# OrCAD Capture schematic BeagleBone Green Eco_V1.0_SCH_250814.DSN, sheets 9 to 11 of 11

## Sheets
9 P04_AM335x 1/3, JTAG: size A2
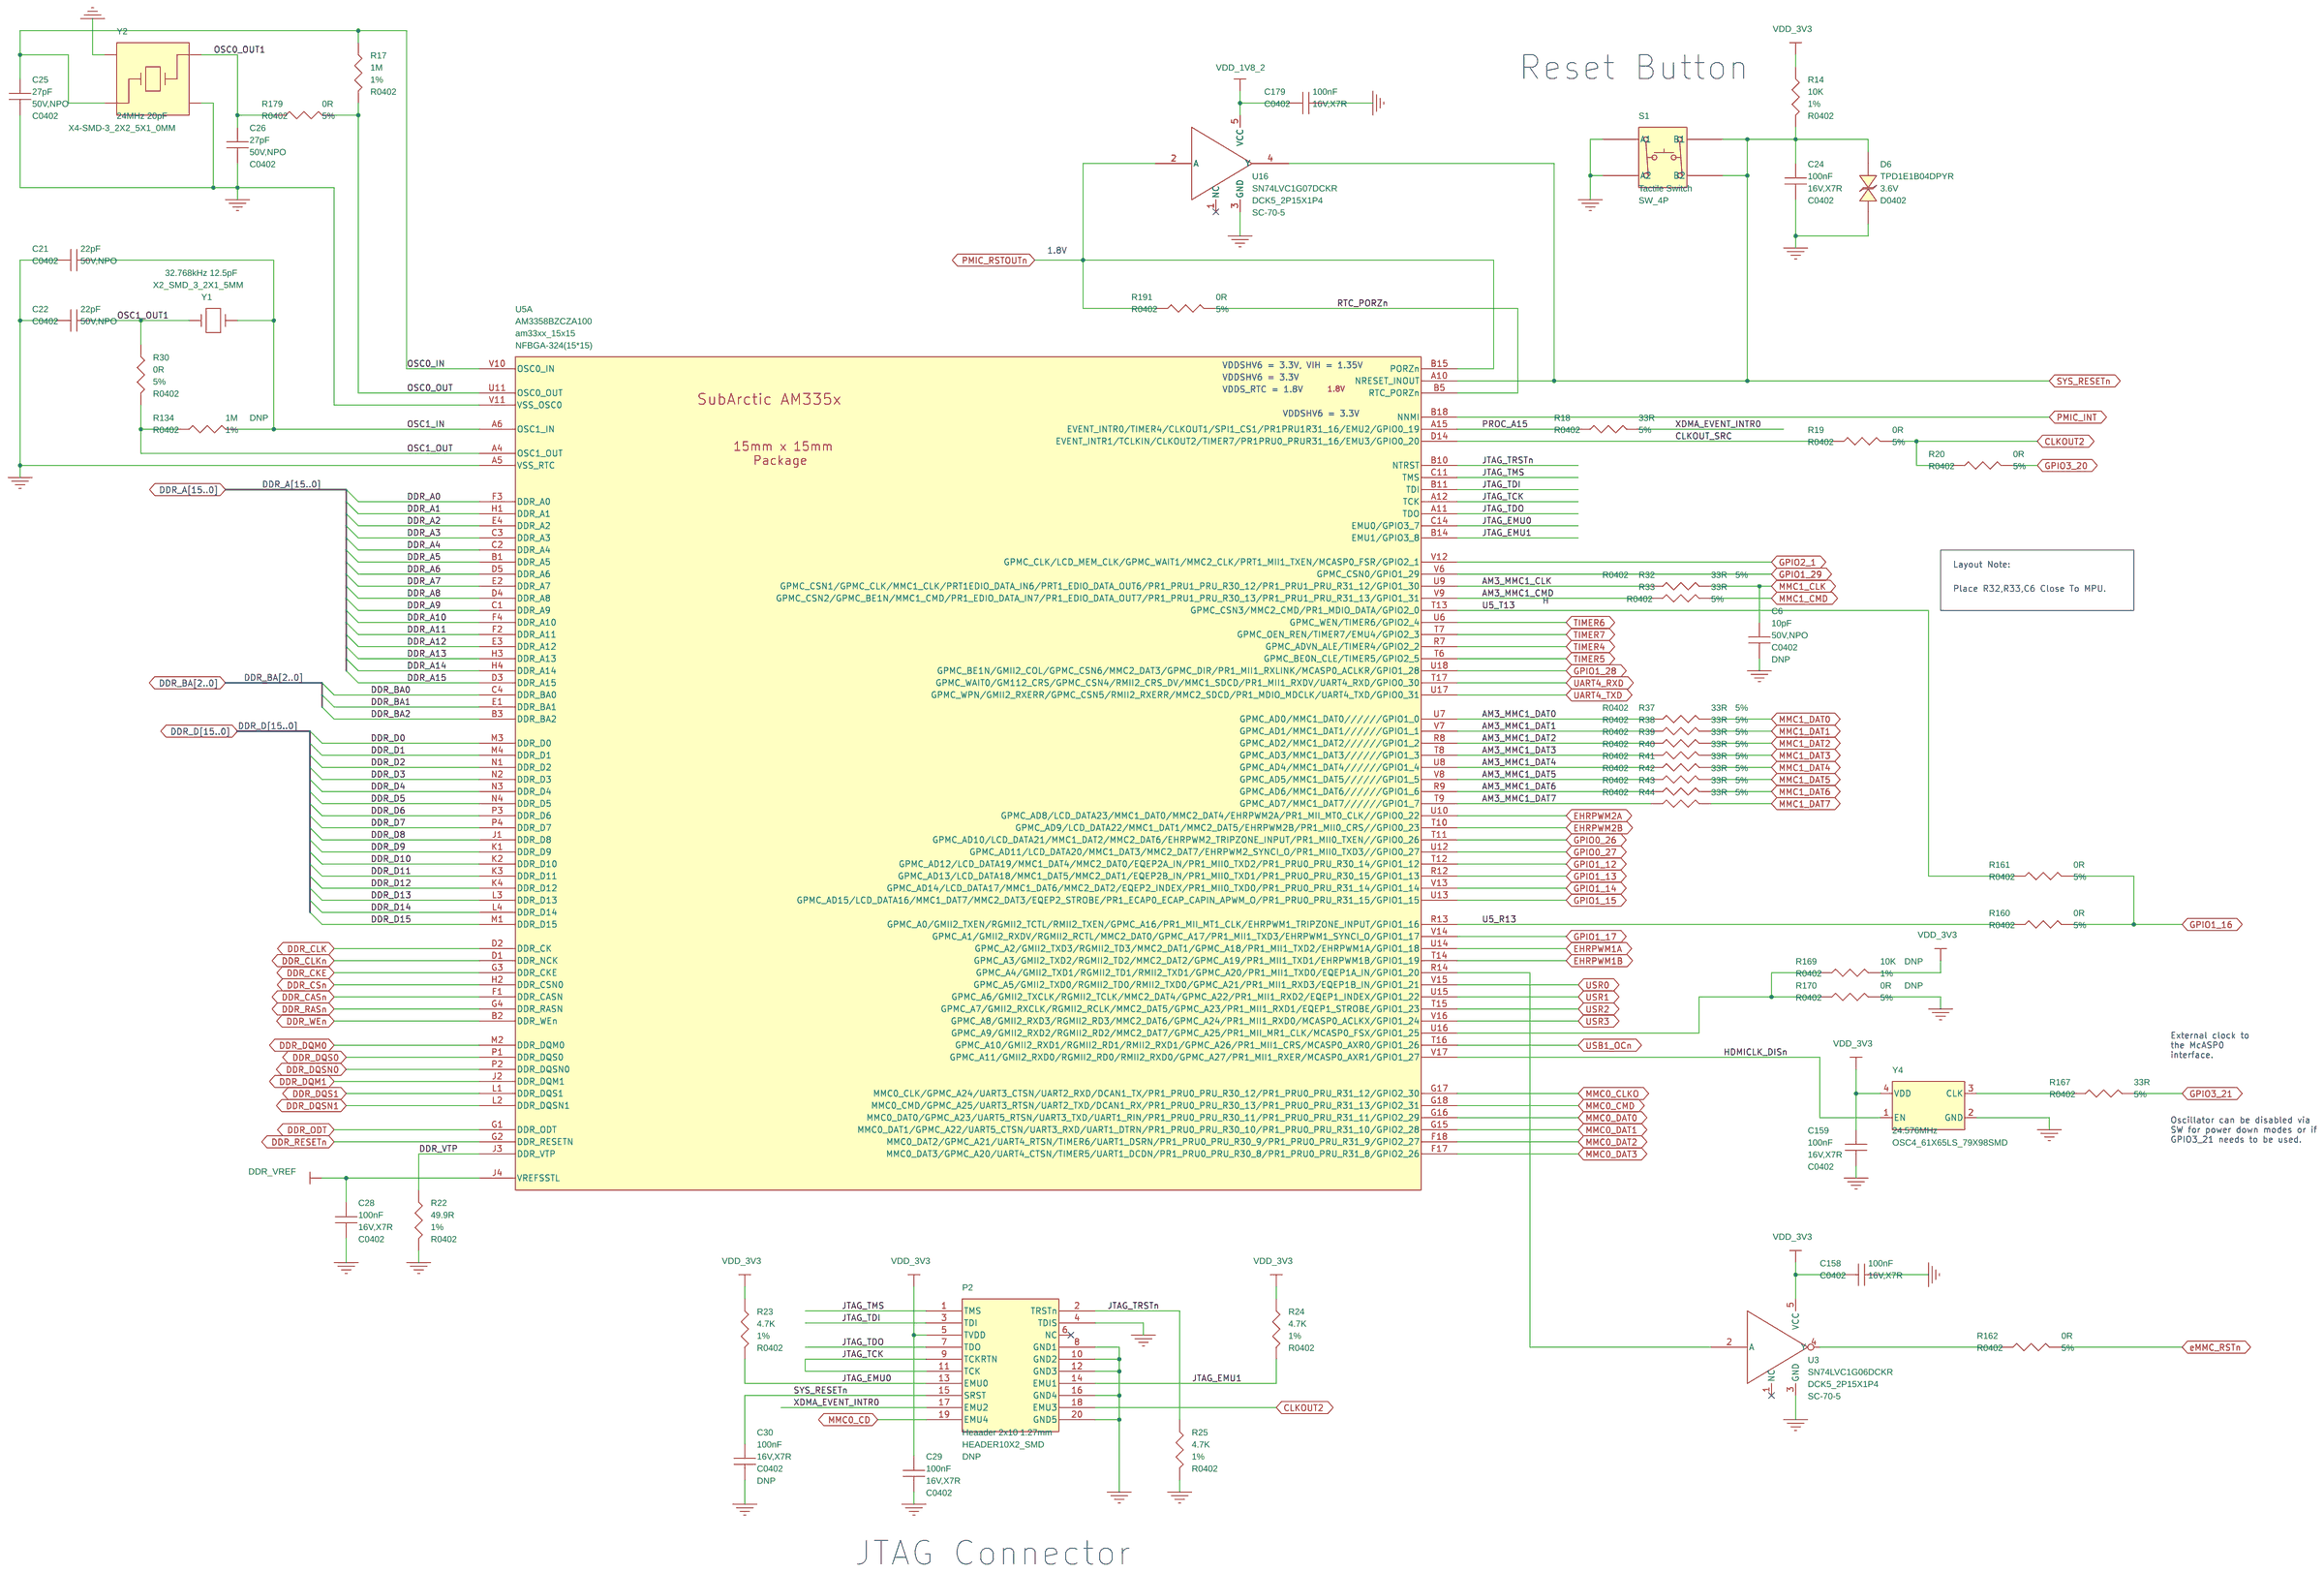
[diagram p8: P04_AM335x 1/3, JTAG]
10 P05_AM335x 2/3, USB, UART: size A2
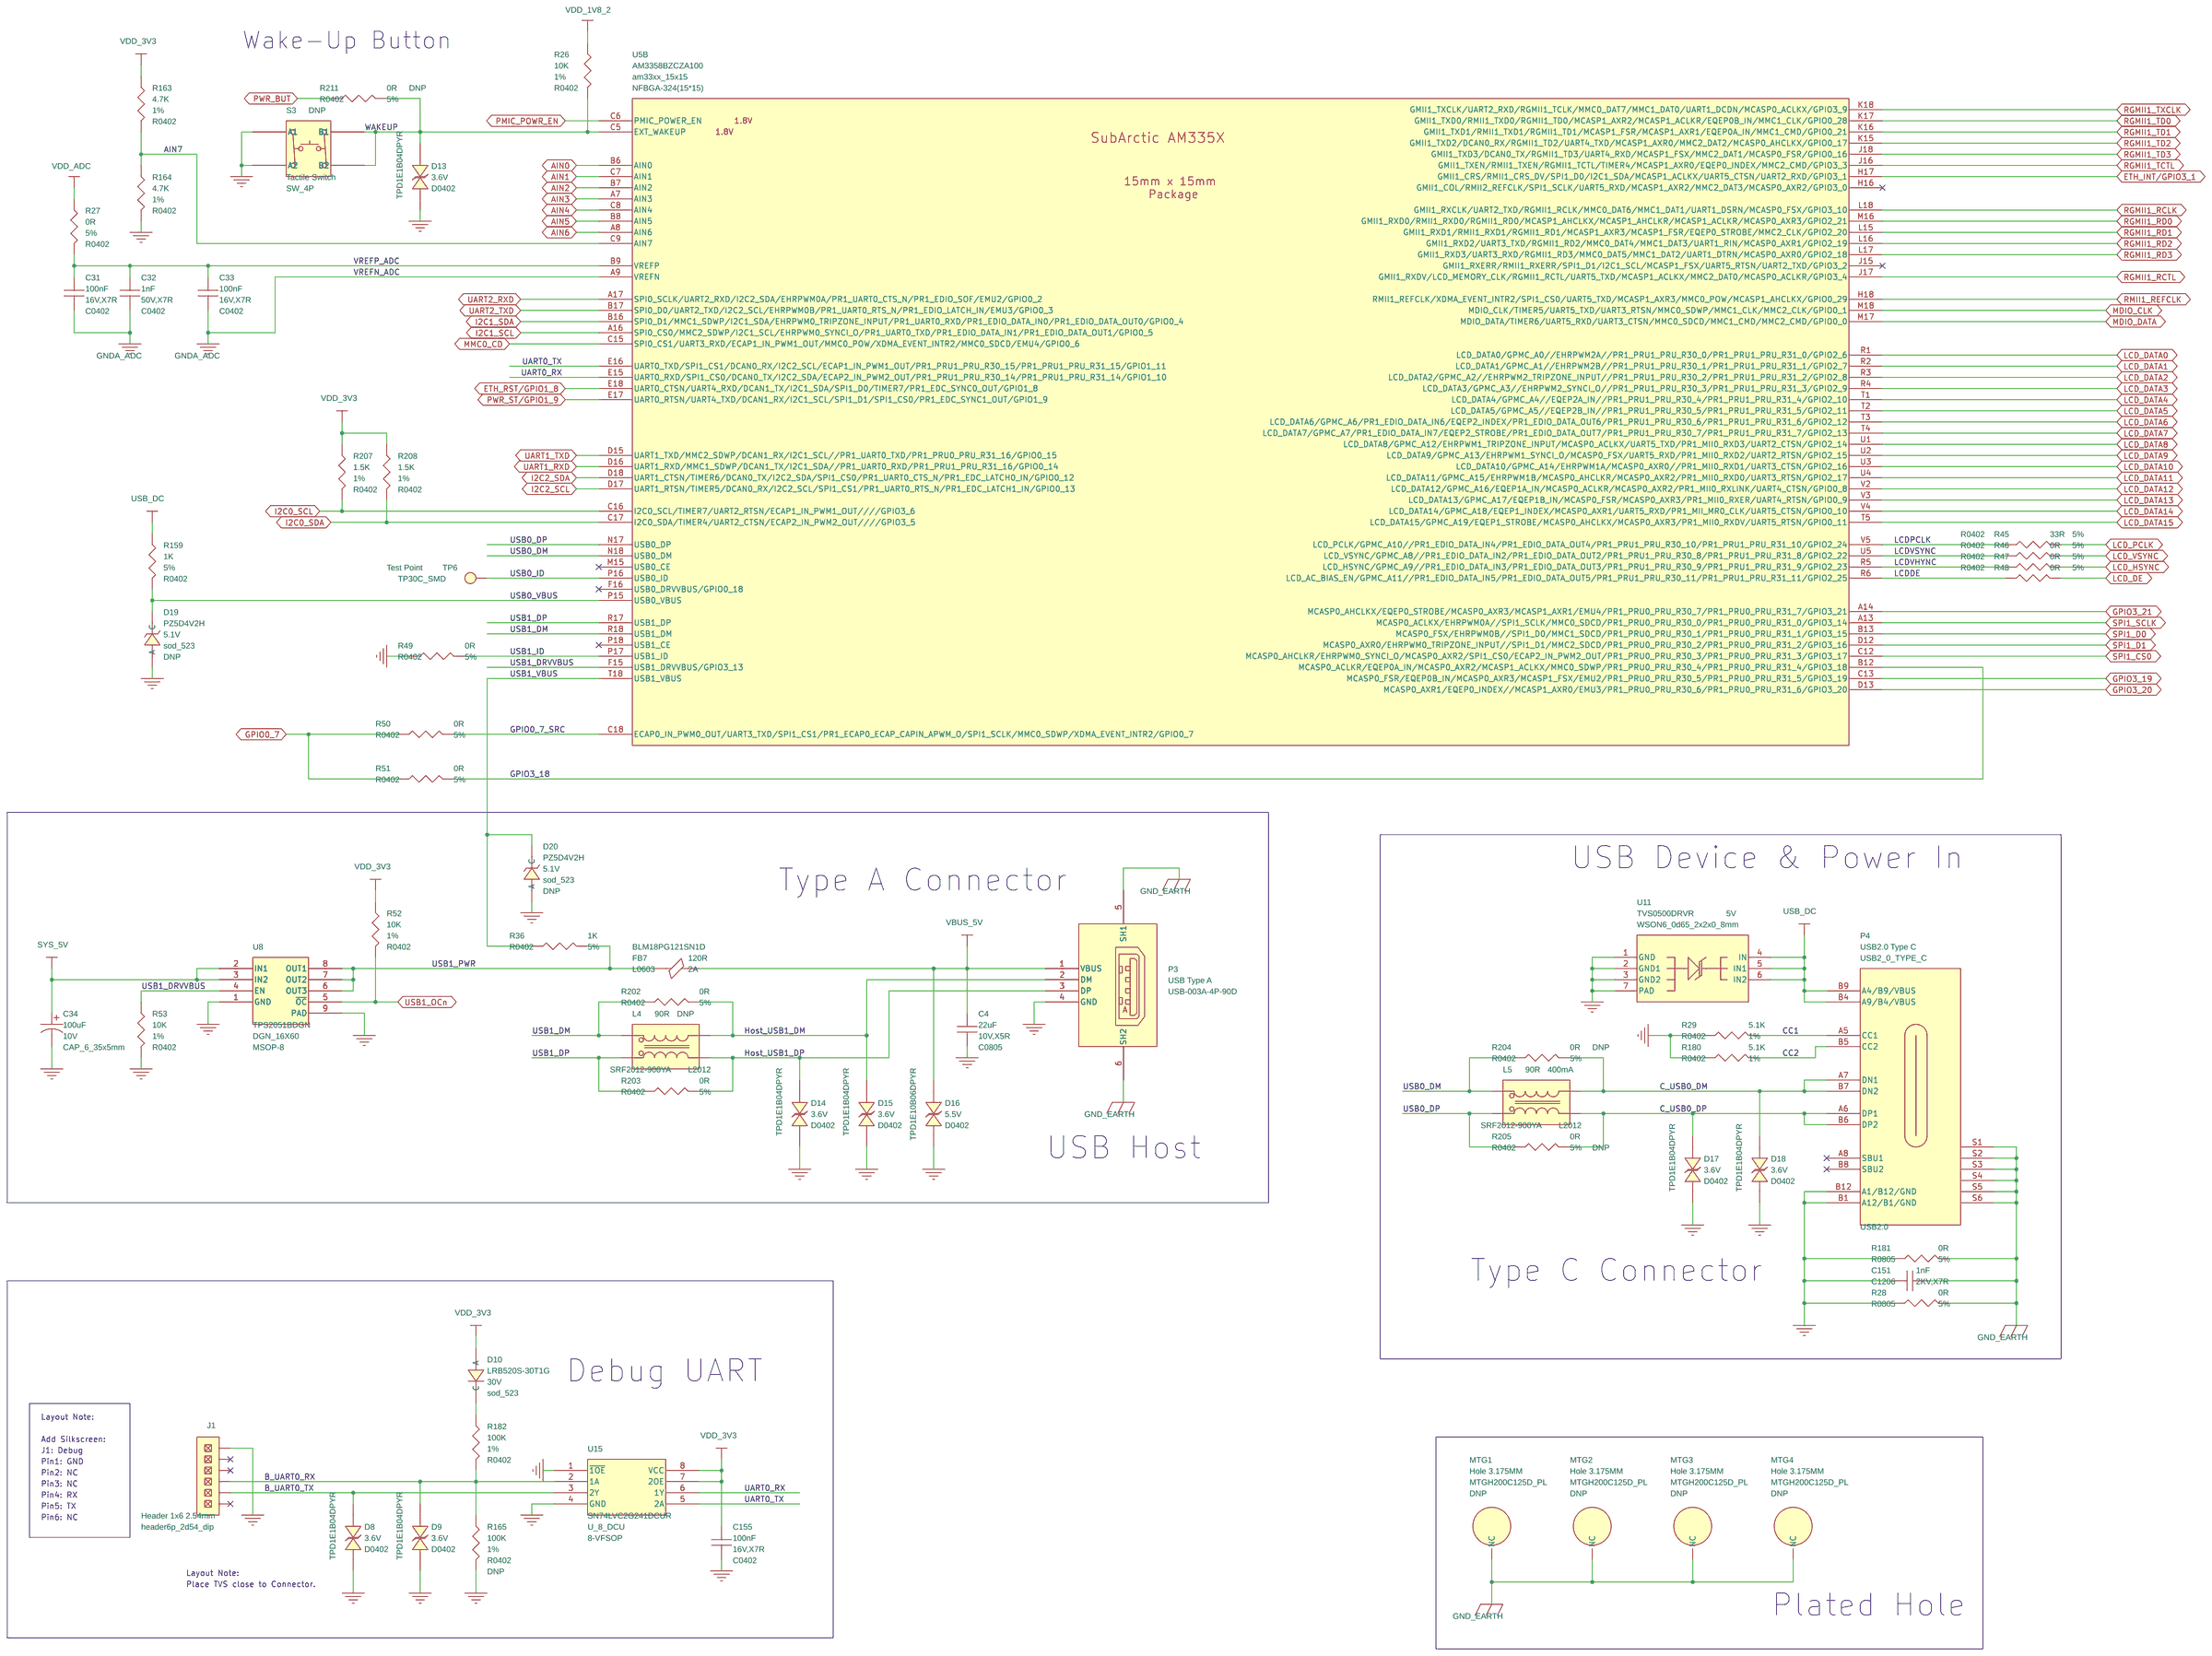
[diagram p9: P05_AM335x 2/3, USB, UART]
11 P06_AM335x 3/3, Power: size A2
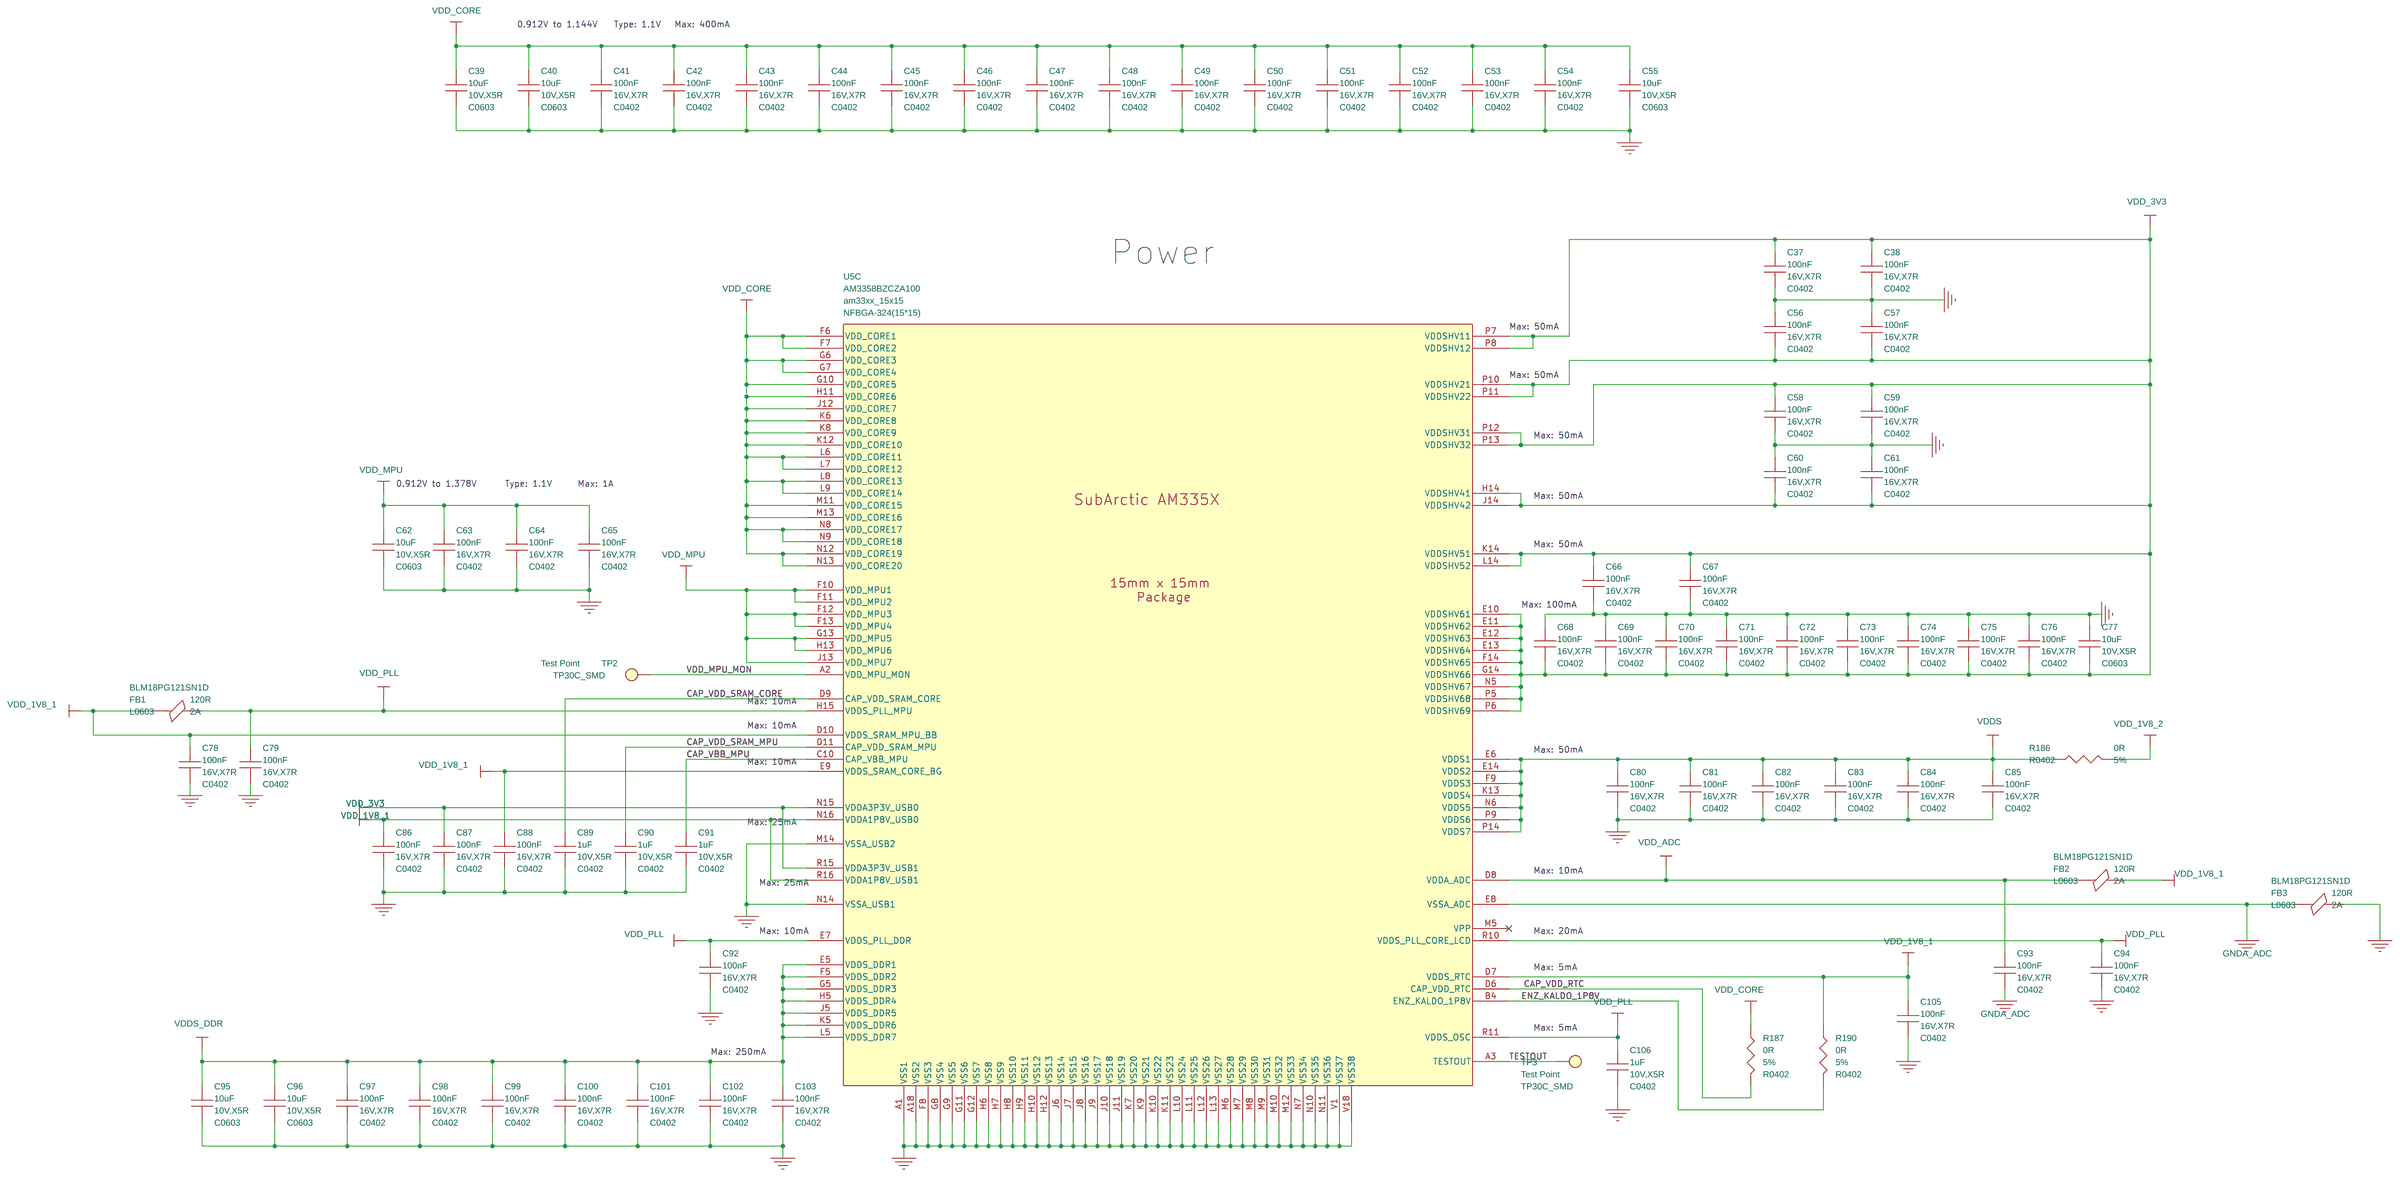
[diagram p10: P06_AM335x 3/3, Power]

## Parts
sheet P04_AM335x 1/3, JTAG
C6  10pF  [C0402]
C21  22pF  [C0402]
C22  22pF  [C0402]
C24  100nF  [C0402]
C25  27pF  [C0402]
C26  27pF  [C0402]
C28  100nF  [C0402]
C29  100nF  [C0402]
C30  100nF  [C0402]
C158  100nF  [C0402]
C159  100nF  [C0402]
C179  100nF  [C0402]
D6  TPD1E1B04DPYR  [D0402]
P2  Heaader 2x10 1.27mm  [HEADER10X2_SMD]
R14  10K  [R0402]
R17  1M  [R0402]
R18  33R  [R0402]
R19  0R  [R0402]
R20  0R  [R0402]
R22  49.9R  [R0402]
R23  4.7K  [R0402]
R24  4.7K  [R0402]
R25  4.7K  [R0402]
R30  0R  [R0402]
R32  33R  [R0402]
R33  33R  [R0402]
R37  33R  [R0402]
R38  33R  [R0402]
R39  33R  [R0402]
R40  33R  [R0402]
R41  33R  [R0402]
R42  33R  [R0402]
R43  33R  [R0402]
R44  33R  [R0402]
R134  1M  [R0402]
R160  0R  [R0402]
R161  0R  [R0402]
R162  0R  [R0402]
R167  33R  [R0402]
R169  10K  [R0402]
R170  0R  [R0402]
R179  0R  [R0402]
R191  0R  [R0402]
S1  Tactile Switch  [SW_4P]
U3  SN74LVC1G06DCKR  [DCK5_2P15X1P4]
U5  AM3358BZCZA100  [am33xx_15x15]  (sections A,B,C)
U16  SN74LVC1G07DCKR  [DCK5_2P15X1P4]
Y1  32.768kHz 12.5pF  [X2_SMD_3_2X1_5MM]
Y2  24MHz 20pF  [X4-SMD-3_2X2_5X1_0MM]
Y4  24.576MHz  [OSC4_61X65LS_79X98SMD]
sheet P05_AM335x 2/3, USB, UART
C4  22uF  [C0805]
C31  100nF  [C0402]
C32  1nF  [C0402]
C33  100nF  [C0402]
C34  100uF  [CAP_6_35x5mm]
C151  1nF  [C1206]
C155  100nF  [C0402]
D8  TPD1E1B04DPYR  [D0402]
D9  TPD1E1B04DPYR  [D0402]
D10  LRB520S-30T1G  [sod_523]
D13  TPD1E1B04DPYR  [D0402]
D14  TPD1E1B04DPYR  [D0402]
D15  TPD1E1B04DPYR  [D0402]
D16  TPD1E10B06DPYR  [D0402]
D17  TPD1E1B04DPYR  [D0402]
D18  TPD1E1B04DPYR  [D0402]
D19  PZ5D4V2H  [sod_523]
D20  PZ5D4V2H  [sod_523]
FB7  120R  [L0603]
J1  Header 1x6 2.54mm  [header6p_2d54_dip]
L4  90R  [L2012]
L5  90R  [L2012]
MTG1  Hole 3.175MM  [MTGH200C125D_PL]
MTG2  Hole 3.175MM  [MTGH200C125D_PL]
MTG3  Hole 3.175MM  [MTGH200C125D_PL]
MTG4  Hole 3.175MM  [MTGH200C125D_PL]
P3  USB Type A  [USB-003A-4P-90D]
P4  USB2.0 Type C  [USB2_0_TYPE_C]
R26  10K  [R0402]
R27  0R  [R0402]
R28  0R  [R0805]
R29  5.1K  [R0402]
R36  1K  [R0402]
R45  33R  [R0402]
R46  0R  [R0402]
R47  0R  [R0402]
R48  0R  [R0402]
R49  0R  [R0402]
R50  0R  [R0402]
R51  0R  [R0402]
R52  10K  [R0402]
R53  10K  [R0402]
R159  1K  [R0402]
R163  4.7K  [R0402]
R164  4.7K  [R0402]
R165  100K  [R0402]
R180  5.1K  [R0402]
R181  0R  [R0805]
R182  100K  [R0402]
R202  0R  [R0402]
R203  0R  [R0402]
R204  0R  [R0402]
R205  0R  [R0402]
R207  1.5K  [R0402]
R208  1.5K  [R0402]
R211  0R  [R0402]
S3  Tactile Switch  [SW_4P]
TP6  Test Point  [TP30C_SMD]
U8  TPS2051BDGN  [DGN_16X60]
U11  TVS0500DRVR  [WSON6_0d65_2x2x0_8mm]
U15  SN74LVC2G241DCUR  [U_8_DCU]
sheet P06_AM335x 3/3, Power
C37  100nF  [C0402]
C38  100nF  [C0402]
C39  10uF  [C0603]
C40  10uF  [C0603]
C41  100nF  [C0402]
C42  100nF  [C0402]
C43  100nF  [C0402]
C44  100nF  [C0402]
C45  100nF  [C0402]
C46  100nF  [C0402]
C47  100nF  [C0402]
C48  100nF  [C0402]
C49  100nF  [C0402]
C50  100nF  [C0402]
C51  100nF  [C0402]
C52  100nF  [C0402]
C53  100nF  [C0402]
C54  100nF  [C0402]
C55  10uF  [C0603]
C56  100nF  [C0402]
C57  100nF  [C0402]
C58  100nF  [C0402]
C59  100nF  [C0402]
C60  100nF  [C0402]
C61  100nF  [C0402]
C62  10uF  [C0603]
C63  100nF  [C0402]
C64  100nF  [C0402]
C65  100nF  [C0402]
C66  100nF  [C0402]
C67  100nF  [C0402]
C68  100nF  [C0402]
C69  100nF  [C0402]
C70  100nF  [C0402]
C71  100nF  [C0402]
C72  100nF  [C0402]
C73  100nF  [C0402]
C74  100nF  [C0402]
C75  100nF  [C0402]
C76  100nF  [C0402]
C77  10uF  [C0603]
C78  100nF  [C0402]
C79  100nF  [C0402]
C80  100nF  [C0402]
C81  100nF  [C0402]
C82  100nF  [C0402]
C83  100nF  [C0402]
C84  100nF  [C0402]
C85  100nF  [C0402]
C86  100nF  [C0402]
C87  100nF  [C0402]
C88  100nF  [C0402]
C89  1uF  [C0402]
C90  1uF  [C0402]
C91  1uF  [C0402]
C92  100nF  [C0402]
C93  100nF  [C0402]
C94  100nF  [C0402]
C95  10uF  [C0603]
C96  10uF  [C0603]
C97  100nF  [C0402]
C98  100nF  [C0402]
C99  100nF  [C0402]
C100  100nF  [C0402]
C101  100nF  [C0402]
C102  100nF  [C0402]
C103  100nF  [C0402]
C105  100nF  [C0402]
C106  1uF  [C0402]
FB1  120R  [L0603]
FB2  120R  [L0603]
FB3  120R  [L0603]
R186  0R  [R0402]
R187  0R  [R0402]
R190  0R  [R0402]
TP2  Test Point  [TP30C_SMD]
TP3  Test Point  [TP30C_SMD]

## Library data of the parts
C6 = CC: SMD CAP Ceramic 10pF-50V-5%-NPO;0402; ASSY: DNP; Manufacturer: YAGEO; Manufacturer Part Number: CC0402JRNPO9BN100; PN: 302010001; Package Size: 0402; Rating: 50V,NPO; Temperature: -55°C to 125°C
C21 C22 = CC: SMD CAP Ceramic 22pF-50V-5%-NPO;0402; Manufacturer: YAGEO; Manufacturer Part Number: CC0402JRNPO9BN220; PN: 302010018; Package Size: 0402; Rating: 50V,NPO; Temperature: -55°C to 125°C
C24 C28 C29 C31 C33 C37 C38 C41-C54 C56-C61 C63-C76 C78-C88 C92-C94 C97-C103 C105 C155 C158 C159 C179 = CC: SMD CAP Ceramic 100nF-16V-10%-X7R;0402; Manufacturer: YAGEO; Manufacturer Part Number: CC0402KRX7R7BB104; PN: 302010004; Package Size: 0402; Rating: 16V,X7R; Temperature: -55°C to 125°C
C25 C26 = CC: SMD CAP Ceramic 27pF-50V-5%-NPO;0402; Manufacturer: YAGEO; Manufacturer Part Number: CC0402JRNPO9BN270; PN: 302010027; Package Size: 0402; Rating: 50V,NPO; Temperature: -55°C to 125°C
C30 = CC: SMD CAP Ceramic 100nF-16V-10%-X7R;0402; ASSY: DNP; Manufacturer: YAGEO; Manufacturer Part Number: CC0402KRX7R7BB104; PN: 302010004; Package Size: 0402; Rating: 16V,X7R; Temperature: -55°C to 125°C
D6 D8 D9 D13-D15 D17 D18 = DIODE_TVS_BI-DIR: SMD TVS DIODE 3.6V-6.4V-1pF;X1SON(2); Manufacturer: TI; PN: 304050798; Package Size: 0402; Rating: 3.6V; Temperature: -40°C to 125°C
P2 = Header_2x10_BB_JTAG: ASSY: DNP; Part Type: Header
R14 R26 R52 R53 = R: SMD RES 10K-1%-1/16W;0402; Manufacturer: YAGEO; Manufacturer Part Number: RC0402FR-0710KL; PN: 301010047; Package Size: 0402; Rating: 1%; Temperature: -55°C to 155°C
R17 = R: SMD RES 1M-1%-1/16W;0402; Manufacturer: YAGEO; Manufacturer Part Number: RC0402FR-071ML; PN: 301010043; Package Size: 0402; Rating: 1%; Temperature: -55°C to 155°C
R18 R32 R33 R37-R45 R167 = R: SMD RES 33R-5%-1/16W;0402; Manufacturer: YAGEO; Manufacturer Part Number: RC0402JR-0733RL; PN: 301010034; Package Size: 0402; Rating: 5%; Temperature: -55°C to 155°C
R19 R20 R27 R46-R51 R160-R162 R186 R187 R190 R191 R202 R203 = R: SMD RES 0R-5%-1/16W;0402; Manufacturer: YAGEO; Manufacturer Part Number: RC0402JR-070RL; PN: 301010000; Package Size: 0402; Rating: 5%; Temperature: -55°C to 155°C
R22 = R: SMD RES 49.9R-1%-1/16W;0402; Manufacturer: YAGEO; Manufacturer Part Number: RC0402FR-0749R9L; PN: 301010041; Package Size: 0402; Rating: 1%; Temperature: -55°C to 155°C
R23-R25 R163 R164 = R: SMD RES;4.7K-1%-1/16W-0402; Manufacturer: YAGEO; Manufacturer Part Number: RC0402FR-074K7L; PN: 301010633; Package Size: 0402; Rating: 1%; Temperature: -55°C to 155°C
R30 R179 = R: SMD RES 0R-5%-1/16W;0402; Manufacturer: YAGEO; Manufacturer Part Number: RC0402JR-070RL; PN: 301010000; Package Size: 0402; Rating: 5%; Temperature: -55°C to 155°C; Datasheet: Y:\01_Cadence_Library\05_Datasheet\301010000_YAGEO_RC0402JR-070RL_Datasheet.pdf
R134 = R: SMD RES 1M-1%-1/16W;0402; ASSY: DNP; Manufacturer: YAGEO; Manufacturer Part Number: RC0402FR-071ML; PN: 301010043; Package Size: 0402; Rating: 1%; Temperature: -55°C to 155°C
R169 = R: SMD RES 10K-1%-1/16W;0402; ASSY: DNP; Manufacturer: YAGEO; Manufacturer Part Number: RC0402FR-0710KL; PN: 301010047; Package Size: 0402; Rating: 1%; Temperature: -55°C to 155°C
R170 R204 R205 R211 = R: SMD RES 0R-5%-1/16W;0402; ASSY: DNP; Manufacturer: YAGEO; Manufacturer Part Number: RC0402JR-070RL; PN: 301010000; Package Size: 0402; Rating: 5%; Temperature: -55°C to 155°C
S1 = Tactile_Switch_4P: SMD Top Button 1.57N;4P-L4.6*W3.2*H2.5mm; Manufacturer: JinBeiLi Electrical; Manufacturer Part Number: TS-1185F-W; PN: 311021800; Package Size: 4.6 x 3.2 x 2.5mm; Temperature: -20°C to 70°C
U3 = SN74LVC1G06DCK: SMD IC Logic;SC-70-5; Manufacturer: TI; PN: 310050077; Package Size: SC-70-5; Temperature: -40°C to 125°C
U5 = AM335X_ZCZ: (BB) SMD IC MCU;NFBGA-324(15*15); Manufacturer: TI; PN: 310010815; Package Size: NFBGA-324(15*15); Temperature: -40°C to 105°C
U16 = SN74LVC1G07DCK: SMD IC Logic;Single Buffer/Driver With Open-Drain Output;SC-70-5; Manufacturer: TI; PN: 310050079; Package Size: SC-70-5; Temperature: -40°C to 125°C
Y1 = XTAL_2P: SMD Crystal 32.768KHz-12.5pF-20ppm-2P-3.2*1.5*0.9mm; Manufacturer: EPSON; Manufacturer Part Number: FC-135 32.7680KA-A3; PN: 306010138; Package Size: 3.2x1.5x0.9mm; Rating: 20ppm,12.5pF; Temperature: -40°C to 85°C
Y2 = XTAL_4P: SMD Crystal 24MHz-20pF-10ppm;4P-SMD-L3.2*W2.5*H0.7mm; Manufacturer: ECEC; Manufacturer Part Number: M24000J407; PN: 306011544; Package Size: 3.2x2.5x0.7mm; Rating: 10ppm,20pF; Temperature: -40°C to 85°C
Y4 = OSC_4P: SMD Oscillator;24.576MHz-50ppm-3.3V-4P-2.5*2*1mm; Manufacturer: ECEC; Manufacturer Part Number: DS24576007; PN: 306020923; Package Size: 2.5x2x1mm; Temperature: -40°C to 85°C
C4 = CC: SMD CAP Ceramic 22uF-10V-10%-X5R;0805; Manufacturer: Samsung; Manufacturer Part Number: CL21A226KPCLRNC; PN: 302012264; Package Size: 0805; Rating: 10V,X5R; Temperature: -55°C to 85°C
C32 = CC: SMD CAP Ceramic 1nF-50V-5%-X7R;0402; Manufacturer: YAGEO; Manufacturer Part Number: CC0402JRX7R9BB102; PN: 302010394; Package Size: 0402; Rating: 50V,X7R; Temperature: -55°C to 125°C
C34 = CT: SMD CAP Aluminum 100uF-10V;D6.3*H5.4mm; Manufacturer: ST; Manufacturer Part Number: CS1A101M-CRE54; PN: 302030050; Package Size: D6.3*H5.4mm; Rating: 10V; Temperature: -40°C to 105°C
C151 = CC: SMD CAP Ceramic 1nF-2kV-10%-X7R;1206; Manufacturer: YAGEO; Manufacturer Part Number: CC1206KKX7RDBB102; PN: 302011962; Package Size: 1206; Rating: 2KV,X7R; Temperature: -55°C to 125°C
D10 = D: SMD Diode Schottky 30V-200mA;SOD-523; Manufacturer: LRC; PN: 304011072; Package Size: SOD-523; Rating: 30V; Temperature: -40°C to 125°C
D16 = DIODE_TVS_BI-DIR: SMD Diode ESD 5.5V-6V-12pF-30KV-30KV;X1SON(2); Manufacturer: TI; PN: 304050312; Package Size: 0402; Rating: 5.5V; Temperature: -40°C to 125°C
D19 D20 = D_zener: SMD Diode Zener;5.1V-500mW;SOD-523; ASSY: DNP; Manufacturer: Prisemi; PN: 304030128; Package Size: SOD-523; Rating: 5.1V; Temperature: -65°C to 150°C
FB1-FB3 FB7 = FB: SMD Ferrite Bead;120R-2A;0603; Manufacturer: Murata; Manufacturer Part Number: BLM18PG121SN1D; PN: 303030024; Package Size: 0603; Rating: 2A; Temperature: -55°C to 125°C
J1 = Header_1x6: DIP Black Male Header VERT;1*6P-2.54-2.5-11.5/3.0mm; Manufacturer: SINOTOP Electronics; Manufacturer Part Number: ST-PH-254-0087-1*6P-6T; PN: 320020078; Package Size: 1*6P-2.54-2.54-11.6/3.0mm; Temperature: -40°C to 105°C
L4 = CL: SMD Common Mode Filter 90R-400mA;4P-L2.0*W1.2*H1.4m; ASSY: DNP; Manufacturer: Bourns; Manufacturer Part Number: SRF2012-900YA; PN: 303050063; Package Size: 2.0x1.2 mm; Rating: 400mA; Temperature: -40°C to 125°C
L5 = CL: SMD Common Mode Filter 90R-400mA;4P-L2.0*W1.2*H1.4m; Manufacturer: Bourns; Manufacturer Part Number: SRF2012-900YA; PN: 303050063; Package Size: 2.0x1.2 mm; Rating: 400mA; Temperature: -40°C to 125°C
MTG1-MTG4 = MHole: Hole Point;3.175MM,5.08MM; ASSY: DNP; Part Type: Mhole
P3 = Single_USB_A: DIP USB A TYPE FMAL;4P-2.0-90D; Manufacturer: SUNGTECH; Manufacturer Part Number: ST-USB-003AW; PN: 320010007; Package Size: 4P-2.0-90D
P4 = USB2.0_Type_C_16+6P#1: SMD USB TYPE C-W/P;12+4P-8.94*7.35*3.26mm; Manufacturer: JinBeiLi Electrical; Manufacturer Part Number: USB-31C-F-16P-L7.35; PN: 320011358; Package Size: 8.94 x 7.55 mm; Rating: USB2.0; Temperature: -30°C to 85°C
R28 R181 = R: SMD RES 0R-5%-1/8W;0805; Manufacturer: YAGEO; Manufacturer Part Number: RC0805JR-070RL; PN: 301010359; Package Size: 0805; Rating: 5%; Temperature: -55°C to 155°C
R29 R180 = R: SMD RES;5.1K-1%-1/16W;0402; Manufacturer: YAGEO; Manufacturer Part Number: RC0402FR-075K1L; PN: 301010495; Package Size: 0402; Rating: 1%; Temperature: -55°C to 155°C
R36 R159 = R: SMD RES 1K-5%-1/16W;0402; Manufacturer: YAGEO; Manufacturer Part Number: RC0402JR-071KL; PN: 301010006; Package Size: 0402; Rating: 5%; Temperature: -55°C to 155°C
R165 = R: SMD RES 100K-1%-1/16W;0402; ASSY: DNP; Manufacturer: YAGEO; Manufacturer Part Number: RC0402FR-07100KL; PN: 301010456; Package Size: 0402; Rating: 1%; Temperature: -55°C to 155°C
R182 = R: SMD RES 100K-1%-1/16W;0402; Manufacturer: YAGEO; Manufacturer Part Number: RC0402FR-07100KL; PN: 301010456; Package Size: 0402; Rating: 1%; Temperature: -55°C to 155°C
R207 R208 = R: SMD RES 1.5K-1%-1/16W;0402; Manufacturer: YAGEO; Manufacturer Part Number: RC0402FR-071K5L; PN: 301010567; Package Size: 0402; Rating: 1%; Temperature: -55°C to 155°C
S3 = Tactile_Switch_4P: SMD Top Button 1.57N;4P-L4.6*W3.2*H2.5mm; ASSY: DNP; Manufacturer: JinBeiLi Electrical; Manufacturer Part Number: TS-1185F-W; PN: 311021800; Package Size: 4.6 x 3.2 x 2.5mm; Temperature: -20°C to 70°C
TP2 TP3 TP6 = Test_Point: Test Point;TP30C_SMD
U8 = TPS2051BDGN: SMD IC PMIC;MSOP-8; Manufacturer: TI; Manufacturer Part Number: TPS2051BDGNR; PN: 310030211; Package Size: MSOP-8; Temperature: -40°C to 85°C
U11 = TVS0500DRVR: SMD Diode TVS 5V;SON-6(2x2mm); Manufacturer: TI; PN: 304051039; Package Size: SON-6(2x2); Rating: 5V; Temperature: -40°C to 125°C
U15 = SN74LVC2G241: SMD IC Logic;Dual Buffer/Driver With 3-State Outputs;US8(8-VFSOP); Manufacturer: TI; PN: 310050078; Package Size: 8-VFSOP; Temperature: -40°C to 125°C
C39 C40 C55 C62 C77 C95 C96 = CC: SMD CAP Ceramic 10uF-10V-10%-X5R;0603; Manufacturer: SAMSUNG; Manufacturer Part Number: CL10A106KP8NNNC; PN: 302013252; Package Size: 0603; Rating: 10V,X5R; Temperature: -55°C to 85°C
C89-C91 C106 = CC: SMD CAP Ceramic 1uF-10V-10%-X5R;0402; Manufacturer: Samsung; Manufacturer Part Number: CL05A105KP5NNNC; PN: 302013249; Package Size: 0402; Rating: 10V,X5R; Temperature: -55°C to 85°C

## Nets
GND: C4.2 C6.2 C21.1 C22.1 C24.2 C25.2 C26.2 C28.2 C29.2 C30.2 C34.2 C37.2 C38.2 C39.2 C40.2 C41.2 C42.2 C43.2 C44.2 C45.2 C46.2 C47.2 C48.2 C49.2 C50.2 C51.2 C52.2 C53.2 C54.2 C55.2 C56.1 C57.1 C58.2 C59.2 C60.1 C61.1 C62.2 C63.2 C64.2 C65.2 C66.2 C67.2 C68.1 C69.1 C70.1 C71.1 C72.1 C73.1 C74.1 C75.1 C76.1 C77.1 C78.2 C79.2 C80.2 C81.2 C82.2 C83.2 C84.2 C85.2 C86.2 C87.2 C88.2 C89.2 C90.2 C91.2 C92.2 C94.2 C95.2 C96.2 C97.2 C98.2 C99.2 C100.2 C101.2 C102.2 C103.2 C105.2 C106.2 C151.1 C155.2 C158.2 C159.2 C179.2 D6.1 D8.1 D9.1 D13.1 D14.1 D15.1 D16.1 D17.1 D18.1 D19.1(A) D20.1(A) FB3.2 J1.1 P2.4(TDIS) P2.8(GND1) P2.10(GND2) P2.12(GND3) P2.16(GND4) P2.20(GND5) P3.4(GND) P4.B1(A12/B1/GND) P4.B12(A1/B12/GND) R22.2 R25.2 R28.1 R29.1 R49.1 R53.2 R164.2 R165.2 R170.2 R180.1 R181.1 S1.1(A1) S1.3(A2) S3.1(A1) S3.3(A2) U3.3(GND) U5.A1(VSS1) U5.A5(VSS_RTC) U5.A18(VSS2) U5.F8(VSS3) U5.G8(VSS4) U5.G9(VSS5) U5.G11(VSS6) U5.G12(VSS7) U5.H6(VSS8) U5.H7(VSS9) U5.H8(VSS10) U5.H9(VSS11) U5.H10(VSS12) U5.H12(VSS13) U5.J6(VSS14) U5.J7(VSS15) U5.J8(VSS16) U5.J9(VSS17) U5.J10(VSS18) U5.J11(VSS19) U5.K7(VSS20) U5.K9(VSS21) U5.K10(VSS22) U5.K11(VSS23) U5.L10(VSS24) U5.L11(VSS25) U5.L12(VSS26) U5.L13(VSS27) U5.M6(VSS28) U5.M7(VSS29) U5.M8(VSS30) U5.M9(VSS31) U5.M10(VSS32) U5.M12(VSS33) U5.M14(VSSA_USB2) U5.N7(VSS34) U5.N10(VSS35) U5.N11(VSS36) U5.N14(VSSA_USB1) U5.V1(VSS37) U5.V11(VSS_OSC0) U5.V18(VSS38) U8.1(GND) U8.9(PAD) U11.1(GND) U11.2(GND1) U11.3(GND2) U11.7(PAD) U15.1(~{1OE}) U15.4(GND) U16.3(GND) Y2.2 Y2.4 Y4.2(GND) ; also on sheet 3 4 5 6 7 8
GND_EARTH: C151.2 MTG1.1(NC) MTG2.1(NC) MTG3.1(NC) MTG4.1(NC) P3.5(SH1) P3.6(SH2) P4.S1 P4.S2 P4.S3 P4.S4 P4.S5 P4.S6 R28.2 R181.2 ; also on sheet 7 8
GNDA_ADC: C31.2 C32.2 C33.2 C93.2 FB3.1 U5.A9(VREFN) U5.E8(VSSA_ADC) ; also on sheet 8
VBUS_5V: C4.1 D16.2 FB7.2 P3.1(VBUS)
VDD_1V8_1: C78.1 C86.1 C88.1 C105.1 FB1.1 FB2.2 R190.1 U5.D7(VDDS_RTC) U5.D10(VDDS_SRAM_MPU_BB) U5.E9(VDDS_SRAM_CORE_BG) U5.N16(VDDA1P8V_USB0) U5.R16(VDDA1P8V_USB1) ; also on sheet 3
VDD_1V8_2: C179.1 R26.1 R186.2 U16.5(VCC) ; also on sheet 3
VDD_3V3: C29.1 C37.1 C38.1 C56.2 C57.2 C58.1 C59.1 C60.2 C61.2 C66.1 C67.1 C68.2 C69.2 C70.2 C71.2 C72.2 C73.2 C74.2 C75.2 C76.2 C77.2 C87.1 C155.1 C158.1 C159.1 D10.1(A) P2.5(TVDD) R14.1 R23.1 R24.1 R52.1 R163.1 R169.2 R207.1 R208.1 U3.5(VCC) U5.E10(VDDSHV61) U5.E11(VDDSHV62) U5.E12(VDDSHV63) U5.E13(VDDSHV64) U5.F14(VDDSHV65) U5.G14(VDDSHV66) U5.H14(VDDSHV41) U5.J14(VDDSHV42) U5.K14(VDDSHV51) U5.L14(VDDSHV52) U5.N5(VDDSHV67) U5.N15(VDDA3P3V_USB0) U5.P5(VDDSHV68) U5.P6(VDDSHV69) U5.P7(VDDSHV11) U5.P8(VDDSHV12) U5.P10(VDDSHV21) U5.P11(VDDSHV22) U5.P12(VDDSHV31) U5.P13(VDDSHV32) U5.R15(VDDA3P3V_USB1) U15.7(2OE) U15.8(VCC) Y4.4(VDD) ; also on sheet 3 4 6 7 8
VDD_ADC: C93.1 FB2.1 R27.1 U5.D8(VDDA_ADC) ; also on sheet 8
VDD_CORE: C39.1 C40.1 C41.1 C42.1 C43.1 C44.1 C45.1 C46.1 C47.1 C48.1 C49.1 C50.1 C51.1 C52.1 C53.1 C54.1 C55.1 R187.1 U5.F6(VDD_CORE1) U5.F7(VDD_CORE2) U5.G6(VDD_CORE3) U5.G7(VDD_CORE4) U5.G10(VDD_CORE5) U5.H11(VDD_CORE6) U5.J12(VDD_CORE7) U5.K6(VDD_CORE8) U5.K8(VDD_CORE9) U5.K12(VDD_CORE10) U5.L6(VDD_CORE11) U5.L7(VDD_CORE12) U5.L8(VDD_CORE13) U5.L9(VDD_CORE14) U5.M11(VDD_CORE15) U5.M13(VDD_CORE16) U5.N8(VDD_CORE17) U5.N9(VDD_CORE18) U5.N12(VDD_CORE19) U5.N13(VDD_CORE20) ; also on sheet 3
VDD_MPU: C62.1 C63.1 C64.1 C65.1 U5.F10(VDD_MPU1) U5.F11(VDD_MPU2) U5.F12(VDD_MPU3) U5.F13(VDD_MPU4) U5.G13(VDD_MPU5) U5.H13(VDD_MPU6) U5.J13(VDD_MPU7) ; also on sheet 3
VDD_MPU_MON: TP2.1(TP) U5.A2(VDD_MPU_MON)
VDD_PLL: C79.1 C92.1 C94.1 C106.1 FB1.2 U5.E7(VDDS_PLL_DDR) U5.H15(VDDS_PLL_MPU) U5.R10(VDDS_PLL_CORE_LCD) U5.R11(VDDS_OSC)
VDDS: C80.1 C81.1 C82.1 C83.1 C84.1 C85.1 R186.1 U5.E6(VDDS1) U5.E14(VDDS2) U5.F9(VDDS3) U5.K13(VDDS4) U5.N6(VDDS5) U5.P9(VDDS6) U5.P14(VDDS7) ; also on sheet 3
VDDS_DDR: C95.1 C96.1 C97.1 C98.1 C99.1 C100.1 C101.1 C102.1 C103.1 U5.E5(VDDS_DDR1) U5.F5(VDDS_DDR2) U5.G5(VDDS_DDR3) U5.H5(VDDS_DDR4) U5.J5(VDDS_DDR5) U5.K5(VDDS_DDR6) U5.L5(VDDS_DDR7) ; also on sheet 3 5
AIN0: U5.B6(AIN0) ; also on sheet 8
AIN1: U5.C7(AIN1) ; also on sheet 8
AIN2: U5.B7(AIN2) ; also on sheet 8
AIN3: U5.A7(AIN3) ; also on sheet 8
AIN4: U5.C8(AIN4) ; also on sheet 8
AIN5: U5.B8(AIN5) ; also on sheet 8
AIN6: U5.A8(AIN6) ; also on sheet 8
AIN7: R163.2 R164.1 U5.C9(AIN7)
AM3_MMC1_CLK: R32.1 U5.U9(GPMC_CSN1/GPMC_CLK/MMC1_CLK/PRT1EDIO_DATA_IN6/PRT1_EDIO_DATA_OUT6/PR1_PRU1_PRU_R30_12/PR1_PRU1_PRU_R31_12/GPIO1_30)
AM3_MMC1_CMD: R33.1 U5.V9(GPMC_CSN2/GPMC_BE1N/MMC1_CMD/PR1_EDIO_DATA_IN7/PR1_EDIO_DATA_OUT7/PR1_PRU1_PRU_R30_13/PR1_PRU1_PRU_R31_13/GPIO1_31)
AM3_MMC1_DAT0: R37.1 U5.U7(GPMC_AD0/MMC1_DAT0//////GPIO1_0)
AM3_MMC1_DAT1: R38.1 U5.V7(GPMC_AD1/MMC1_DAT1//////GPIO1_1)
AM3_MMC1_DAT2: R39.1 U5.R8(GPMC_AD2/MMC1_DAT2//////GPIO1_2)
AM3_MMC1_DAT3: R40.1 U5.T8(GPMC_AD3/MMC1_DAT3//////GPIO1_3)
AM3_MMC1_DAT4: R41.1 U5.U8(GPMC_AD4/MMC1_DAT4//////GPIO1_4)
AM3_MMC1_DAT5: R42.1 U5.V8(GPMC_AD5/MMC1_DAT5//////GPIO1_5)
AM3_MMC1_DAT6: R43.1 U5.R9(GPMC_AD6/MMC1_DAT6//////GPIO1_6)
AM3_MMC1_DAT7: R44.1 U5.T9(GPMC_AD7/MMC1_DAT7//////GPIO1_7)
B_UART0_RX: D9.2 J1.4 R165.1 R182.2 U15.2(1A)
B_UART0_TX: D8.2 J1.5 U15.3(2Y)
C_USB0_DM: D18.2 L5.2 P4.A7(DN1) P4.B7(DN2) R204.2
C_USB0_DP: D17.2 L5.3 P4.A6(DP1) P4.B6(DP2) R205.2
CAP_VBB_MPU: C91.1 U5.C10(CAP_VBB_MPU)
CAP_VDD_RTC: R187.2 U5.D6(CAP_VDD_RTC)
CAP_VDD_SRAM_CORE: C89.1 U5.D9(CAP_VDD_SRAM_CORE)
CAP_VDD_SRAM_MPU: C90.1 U5.D11(CAP_VDD_SRAM_MPU)
CC1: P4.A5(CC1) R29.2
CC2: P4.B5(CC2) R180.2
CLKOUT2: P2.18(EMU3) R19.2 R20.1 ; also on sheet 8
CLKOUT_SRC: R19.1 U5.D14(EVENT_INTR1/TCLKIN/CLKOUT2/TIMER7/PR1PRU0_PRUR31_16/EMU3/GPIO0_20)
DDR_A0: U5.F3(DDR_A0) ; also on sheet 5
DDR_A1: U5.H1(DDR_A1) ; also on sheet 5
DDR_A2: U5.E4(DDR_A2) ; also on sheet 5
DDR_A3: U5.C3(DDR_A3) ; also on sheet 5
DDR_A4: U5.C2(DDR_A4) ; also on sheet 5
DDR_A5: U5.B1(DDR_A5) ; also on sheet 5
DDR_A6: U5.D5(DDR_A6) ; also on sheet 5
DDR_A7: U5.E2(DDR_A7) ; also on sheet 5
DDR_A8: U5.D4(DDR_A8) ; also on sheet 5
DDR_A9: U5.C1(DDR_A9) ; also on sheet 5
DDR_A10: U5.F4(DDR_A10) ; also on sheet 5
DDR_A11: U5.F2(DDR_A11) ; also on sheet 5
DDR_A12: U5.E3(DDR_A12) ; also on sheet 5
DDR_A13: U5.H3(DDR_A13) ; also on sheet 5
DDR_A14: U5.H4(DDR_A14) ; also on sheet 5
DDR_A15: U5.D3(DDR_A15) ; also on sheet 5
DDR_BA0: U5.C4(DDR_BA0) ; also on sheet 5
DDR_BA1: U5.E1(DDR_BA1) ; also on sheet 5
DDR_BA2: U5.B3(DDR_BA2) ; also on sheet 5
DDR_CASn: U5.F1(DDR_CASN) ; also on sheet 5
DDR_CKE: U5.G3(DDR_CKE) ; also on sheet 5
DDR_CLK: U5.D2(DDR_CK) ; also on sheet 5
DDR_CLKn: U5.D1(DDR_NCK) ; also on sheet 5
DDR_CSn: U5.H2(DDR_CSN0) ; also on sheet 5
DDR_D0: U5.M3(DDR_D0) ; also on sheet 5
DDR_D1: U5.M4(DDR_D1) ; also on sheet 5
DDR_D2: U5.N1(DDR_D2) ; also on sheet 5
DDR_D3: U5.N2(DDR_D3) ; also on sheet 5
DDR_D4: U5.N3(DDR_D4) ; also on sheet 5
DDR_D5: U5.N4(DDR_D5) ; also on sheet 5
DDR_D6: U5.P3(DDR_D6) ; also on sheet 5
DDR_D7: U5.P4(DDR_D7) ; also on sheet 5
DDR_D8: U5.J1(DDR_D8) ; also on sheet 5
DDR_D9: U5.K1(DDR_D9) ; also on sheet 5
DDR_D10: U5.K2(DDR_D10) ; also on sheet 5
DDR_D11: U5.K3(DDR_D11) ; also on sheet 5
DDR_D12: U5.K4(DDR_D12) ; also on sheet 5
DDR_D13: U5.L3(DDR_D13) ; also on sheet 5
DDR_D14: U5.L4(DDR_D14) ; also on sheet 5
DDR_D15: U5.M1(DDR_D15) ; also on sheet 5
DDR_DQM0: U5.M2(DDR_DQM0) ; also on sheet 5
DDR_DQM1: U5.J2(DDR_DQM1) ; also on sheet 5
DDR_DQS0: U5.P1(DDR_DQS0) ; also on sheet 5
DDR_DQS1: U5.L1(DDR_DQS1) ; also on sheet 5
DDR_DQSN0: U5.P2(DDR_DQSN0) ; also on sheet 5
DDR_DQSN1: U5.L2(DDR_DQSN1) ; also on sheet 5
DDR_ODT: U5.G1(DDR_ODT) ; also on sheet 5
DDR_RASn: U5.G4(DDR_RASN) ; also on sheet 5
DDR_RESETn: U5.G2(DDR_RESETN) ; also on sheet 5
DDR_VREF: C28.1 U5.J4(VREFSSTL) ; also on sheet 5
DDR_VTP: R22.1 U5.J3(DDR_VTP)
DDR_WEn: U5.B2(DDR_WEn) ; also on sheet 5
EHRPWM1A: U5.U14(GPMC_A2/GMII2_TXD3/RGMII2_TD3/MMC2_DAT1/GPMC_A18/PR1_MII1_TXD2/EHRPWM1A/GPIO1_18) ; also on sheet 8
EHRPWM1B: U5.T14(GPMC_A3/GMII2_TXD2/RGMII2_TD2/MMC2_DAT2/GPMC_A19/PR1_MII1_TXD1/EHRPWM1B/GPIO1_19) ; also on sheet 8
EHRPWM2A: U5.U10(GPMC_AD8/LCD_DATA23/MMC1_DAT0/MMC2_DAT4/EHRPWM2A/PR1_MII_MT0_CLK//GPIO0_22) ; also on sheet 8
EHRPWM2B: U5.T10(GPMC_AD9/LCD_DATA22/MMC1_DAT1/MMC2_DAT5/EHRPWM2B/PR1_MII0_CRS//GPIO0_23) ; also on sheet 8
eMMC_RSTn: R162.2 ; also on sheet 6
ENZ_KALDO_1P8V: R190.2 U5.B4(ENZ_KALDO_1P8V)
ETH_INT/GPIO3_1: U5.H17(GMII1_CRS/RMII1_CRS_DV/SPI1_D0/I2C1_SDA/MCASP1_ACLKX/UART5_CTSN/UART2_RXD/GPIO3_1) ; also on sheet 7
ETH_RST/GPIO1_8: U5.E18(UART0_CTSN/UART4_RXD/DCAN1_TX/I2C1_SDA/SPI1_D0/TIMER7/PR1_EDC_SYNC0_OUT/GPIO1_8) ; also on sheet 7
GPIO0_7: R50.1 R51.1 ; also on sheet 8
GPIO0_7_SRC: R50.2 U5.C18(ECAP0_IN_PWM0_OUT/UART3_TXD/SPI1_CS1/PR1_ECAP0_ECAP_CAPIN_APWM_O/SPI1_SCLK/MMC0_SDWP/XDMA_EVENT_INTR2/GPIO0_7)
GPIO0_26: U5.T11(GPMC_AD10/LCD_DATA21/MMC1_DAT2/MMC2_DAT6/EHRPWM2_TRIPZONE_INPUT/PR1_MII0_TXEN//GPIO0_26) ; also on sheet 8
GPIO0_27: U5.U12(GPMC_AD11/LCD_DATA20/MMC1_DAT3/MMC2_DAT7/EHRPWM2_SYNCI_O/PR1_MII0_TXD3//GPIO0_27) ; also on sheet 8
GPIO1_12: U5.T12(GPMC_AD12/LCD_DATA19/MMC1_DAT4/MMC2_DAT0/EQEP2A_IN/PR1_MII0_TXD2/PR1_PRU0_PRU_R30_14/GPIO1_12) ; also on sheet 8
GPIO1_13: U5.R12(GPMC_AD13/LCD_DATA18/MMC1_DAT5/MMC2_DAT1/EQEP2B_IN/PR1_MII0_TXD1/PR1_PRU0_PRU_R30_15/GPIO1_13) ; also on sheet 8
GPIO1_14: U5.V13(GPMC_AD14/LCD_DATA17/MMC1_DAT6/MMC2_DAT2/EQEP2_INDEX/PR1_MII0_TXD0/PR1_PRU0_PRU_R31_14/GPIO1_14) ; also on sheet 8
GPIO1_15: U5.U13(GPMC_AD15/LCD_DATA16/MMC1_DAT7/MMC2_DAT3/EQEP2_STROBE/PR1_ECAP0_ECAP_CAPIN_APWM_O/PR1_PRU0_PRU_R31_15/GPIO1_15) ; also on sheet 8
GPIO1_16: R160.2 R161.2 ; also on sheet 8
GPIO1_17: U5.V14(GPMC_A1/GMII2_RXDV/RGMII2_RCTL/MMC2_DAT0/GPMC_A17/PR1_MII1_TXD3/EHRPWM1_SYNCI_O/GPIO1_17) ; also on sheet 8
GPIO1_28: U5.U18(GPMC_BE1N/GMII2_COL/GPMC_CSN6/MMC2_DAT3/GPMC_DIR/PR1_MII1_RXLINK/MCASP0_ACLKR/GPIO1_28) ; also on sheet 8
GPIO1_29: U5.V6(GPMC_CSN0/GPIO1_29) ; also on sheet 8
GPIO2_1: U5.V12(GPMC_CLK/LCD_MEM_CLK/GPMC_WAIT1/MMC2_CLK/PRT1_MII1_TXEN/MCASP0_FSR/GPIO2_1) ; also on sheet 8
GPIO3_18: R51.2 U5.B12(MCASP0_ACLKR/EQEP0A_IN/MCASP0_AXR2/MCASP1_ACLKX/MMC0_SDWP/PR1_PRU0_PRU_R30_4/PR1_PRU0_PRU_R31_4/GPIO3_18)
GPIO3_19: U5.C13(MCASP0_FSR/EQEP0B_IN/MCASP0_AXR3/MCASP1_FSX/EMU2/PR1_PRU0_PRU_R30_5/PR1_PRU0_PRU_R31_5/GPIO3_19) ; also on sheet 8
GPIO3_20: R20.2 U5.D13(MCASP0_AXR1/EQEP0_INDEX//MCASP1_AXR0/EMU3/PR1_PRU0_PRU_R30_6/PR1_PRU0_PRU_R31_6/GPIO3_20)
GPIO3_21: R167.2 U5.A14(MCASP0_AHCLKX/EQEP0_STROBE/MCASP0_AXR3/MCASP1_AXR1/EMU4/PR1_PRU0_PRU_R30_7/PR1_PRU0_PRU_R31_7/GPIO3_21) ; also on sheet 8
HDMICLK_DISn: U5.V17(GPMC_A11/GMII2_RXD0/RGMII2_RD0/RMII2_RXD0/GPMC_A27/PR1_MII1_RXER/MCASP0_AXR1/GPIO1_27) Y4.1(EN)
Host_USB1_DM: D15.2 L4.2 P3.2(DM) R202.2
Host_USB1_DP: D14.2 L4.3 P3.3(DP) R203.2
I2C0_SCL: R207.2 U5.C16(I2C0_SCL/TIMER7/UART2_RTSN/ECAP1_IN_PWM1_OUT////GPIO3_6) ; also on sheet 3 8
I2C0_SDA: R208.2 U5.C17(I2C0_SDA/TIMER4/UART2_CTSN/ECAP2_IN_PWM2_OUT////GPIO3_5) ; also on sheet 3 8
I2C1_SCL: U5.A16(SPI0_CS0/MMC2_SDWP/I2C1_SCL/EHRPWM0_SYNCI_O/PR1_UART0_TXD/PR1_EDIO_DATA_IN1/PR1_EDIO_DATA_OUT1/GPIO0_5) ; also on sheet 8
I2C1_SDA: U5.B16(SPI0_D1/MMC1_SDWP/I2C1_SDA/EHRPWM0_TRIPZONE_INPUT/PR1_UART0_RXD/PR1_EDIO_DATA_IN0/PR1_EDIO_DATA_OUT0/GPIO0_4) ; also on sheet 8
I2C2_SCL: U5.D17(UART1_RTSN/TIMER5/DCAN0_RX/I2C2_SCL/SPI1_CS1/PR1_UART0_RTS_N/PR1_EDC_LATCH1_IN/GPIO0_13) ; also on sheet 8
I2C2_SDA: U5.D18(UART1_CTSN/TIMER6/DCAN0_TX/I2C2_SDA/SPI1_CS0/PR1_UART0_CTS_N/PR1_EDC_LATCH0_IN/GPIO0_12) ; also on sheet 8
JTAG_EMU0: P2.13(EMU0) R23.2 U5.C14(EMU0/GPIO3_7)
JTAG_EMU1: P2.14(EMU1) R24.2 U5.B14(EMU1/GPIO3_8)
JTAG_TCK: P2.9(TCKRTN) P2.11(TCK) U5.A12(TCK)
JTAG_TDI: P2.3(TDI) U5.B11(TDI)
JTAG_TDO: P2.7(TDO) U5.A11(TDO)
JTAG_TMS: P2.1(TMS) U5.C11(TMS)
JTAG_TRSTn: P2.2(TRSTn) R25.1 U5.B10(NTRST)
LCD_DATA0: U5.R1(LCD_DATA0/GPMC_A0//EHRPWM2A//PR1_PRU1_PRU_R30_0/PR1_PRU1_PRU_R31_0/GPIO2_6) ; also on sheet 4 8
LCD_DATA1: U5.R2(LCD_DATA1/GPMC_A1//EHRPWM2B//PR1_PRU1_PRU_R30_1/PR1_PRU1_PRU_R31_1/GPIO2_7) ; also on sheet 4 8
LCD_DATA2: U5.R3(LCD_DATA2/GPMC_A2//EHRPWM2_TRIPZONE_INPUT//PR1_PRU1_PRU_R30_2/PR1_PRU1_PRU_R31_2/GPIO2_8) ; also on sheet 4 8
LCD_DATA3: U5.R4(LCD_DATA3/GPMC_A3//EHRPWM2_SYNCI_O//PR1_PRU1_PRU_R30_3/PR1_PRU1_PRU_R31_3/GPIO2_9) ; also on sheet 4 8
LCD_DATA4: U5.T1(LCD_DATA4/GPMC_A4//EQEP2A_IN//PR1_PRU1_PRU_R30_4/PR1_PRU1_PRU_R31_4/GPIO2_10) ; also on sheet 4 8
LCD_DATA5: U5.T2(LCD_DATA5/GPMC_A5//EQEP2B_IN//PR1_PRU1_PRU_R30_5/PR1_PRU1_PRU_R31_5/GPIO2_11) ; also on sheet 4 8
LCD_DATA6: U5.T3(LCD_DATA6/GPMC_A6/PR1_EDIO_DATA_IN6/EQEP2_INDEX/PR1_EDIO_DATA_OUT6/PR1_PRU1_PRU_R30_6/PR1_PRU1_PRU_R31_6/GPIO2_12) ; also on sheet 4 8
LCD_DATA7: U5.T4(LCD_DATA7/GPMC_A7/PR1_EDIO_DATA_IN7/EQEP2_STROBE/PR1_EDIO_DATA_OUT7/PR1_PRU1_PRU_R30_7/PR1_PRU1_PRU_R31_7/GPIO2_13) ; also on sheet 4 8
LCD_DATA8: U5.U1(LCD_DATA8/GPMC_A12/EHRPWM1_TRIPZONE_INPUT/MCASP0_ACLKX/UART5_TXD/PR1_MII0_RXD3/UART2_CTSN/GPIO2_14) ; also on sheet 4 8
LCD_DATA9: U5.U2(LCD_DATA9/GPMC_A13/EHRPWM1_SYNCI_O/MCASP0_FSX/UART5_RXD/PR1_MII0_RXD2/UART2_RTSN/GPIO2_15) ; also on sheet 4 8
LCD_DATA10: U5.U3(LCD_DATA10/GPMC_A14/EHRPWM1A/MCASP0_AXR0//PR1_MII0_RXD1/UART3_CTSN/GPIO2_16) ; also on sheet 4 8
LCD_DATA11: U5.U4(LCD_DATA11/GPMC_A15/EHRPWM1B/MCASP0_AHCLKR/MCASP0_AXR2/PR1_MII0_RXD0/UART3_RTSN/GPIO2_17) ; also on sheet 4 8
LCD_DATA12: U5.V2(LCD_DATA12/GPMC_A16/EQEP1A_IN/MCASP0_ACLKR/MCASP0_AXR2/PR1_MII0_RXLINK/UART4_CTSN/GPIO0_8) ; also on sheet 4 8
LCD_DATA13: U5.V3(LCD_DATA13/GPMC_A17/EQEP1B_IN/MCASP0_FSR/MCASP0_AXR3/PR1_MII0_RXER/UART4_RTSN/GPIO0_9) ; also on sheet 4 8
LCD_DATA14: U5.V4(LCD_DATA14/GPMC_A18/EQEP1_INDEX/MCASP0_AXR1/UART5_RXD/PR1_MII_MR0_CLK/UART5_CTSN/GPIO0_10) ; also on sheet 4 8
LCD_DATA15: U5.T5(LCD_DATA15/GPMC_A19/EQEP1_STROBE/MCASP0_AHCLKX/MCASP0_AXR3/PR1_MII0_RXDV/UART5_RTSN/GPIO0_11) ; also on sheet 4 8
LCD_DE: R48.2 ; also on sheet 8
LCD_HSYNC: R47.2 ; also on sheet 8
LCD_PCLK: R45.2 ; also on sheet 8
LCD_VSYNC: R46.2 ; also on sheet 8
LCDDE: R48.1 U5.R6(LCD_AC_BIAS_EN/GPMC_A11//PR1_EDIO_DATA_IN5/PR1_EDIO_DATA_OUT5/PR1_PRU1_PRU_R30_11/PR1_PRU1_PRU_R31_11/GPIO2_25)
LCDPCLK: R45.1 U5.V5(LCD_PCLK/GPMC_A10//PR1_EDIO_DATA_IN4/PR1_EDIO_DATA_OUT4/PR1_PRU1_PRU_R30_10/PR1_PRU1_PRU_R31_10/GPIO2_24)
LCDVHYNC: R47.1 U5.R5(LCD_HSYNC/GPMC_A9//PR1_EDIO_DATA_IN3/PR1_EDIO_DATA_OUT3/PR1_PRU1_PRU_R30_9/PR1_PRU1_PRU_R31_9/GPIO2_23)
LCDVSYNC: R46.1 U5.U5(LCD_VSYNC/GPMC_A8//PR1_EDIO_DATA_IN2/PR1_EDIO_DATA_OUT2/PR1_PRU1_PRU_R30_8/PR1_PRU1_PRU_R31_8/GPIO2_22)
MDIO_CLK: U5.M18(MDIO_CLK/TIMER5/UART5_TXD/UART3_RTSN/MMC0_SDWP/MMC1_CLK/MMC2_CLK/GPIO0_1) ; also on sheet 7
MDIO_DATA: U5.M17(MDIO_DATA/TIMER6/UART5_RXD/UART3_CTSN/MMC0_SDCD/MMC1_CMD/MMC2_CMD/GPIO0_0) ; also on sheet 7
MMC0_CD: P2.19(EMU4) U5.C15(SPI0_CS1/UART3_RXD/ECAP1_IN_PWM1_OUT/MMC0_POW/XDMA_EVENT_INTR2/MMC0_SDCD/EMU4/GPIO0_6) ; also on sheet 8
MMC0_CLKO: U5.G17(MMC0_CLK/GPMC_A24/UART3_CTSN/UART2_RXD/DCAN1_TX/PR1_PRU0_PRU_R30_12/PR1_PRU0_PRU_R31_12/GPIO2_30) ; also on sheet 8
MMC0_CMD: U5.G18(MMC0_CMD/GPMC_A25/UART3_RTSN/UART2_TXD/DCAN1_RX/PR1_PRU0_PRU_R30_13/PR1_PRU0_PRU_R31_13/GPIO2_31) ; also on sheet 8
MMC0_DAT0: U5.G16(MMC0_DAT0/GPMC_A23/UART5_RTSN/UART3_TXD/UART1_RIN/PR1_PRU0_PRU_R30_11/PR1_PRU0_PRU_R31_11/GPIO2_29) ; also on sheet 8
MMC0_DAT1: U5.G15(MMC0_DAT1/GPMC_A22/UART5_CTSN/UART3_RXD/UART1_DTRN/PR1_PRU0_PRU_R30_10/PR1_PRU0_PRU_R31_10/GPIO2_28) ; also on sheet 8
MMC0_DAT2: U5.F18(MMC0_DAT2/GPMC_A21/UART4_RTSN/TIMER6/UART1_DSRN/PR1_PRU0_PRU_R30_9/PR1_PRU0_PRU_R31_9/GPIO2_27) ; also on sheet 8
MMC0_DAT3: U5.F17(MMC0_DAT3/GPMC_A20/UART4_CTSN/TIMER5/UART1_DCDN/PR1_PRU0_PRU_R30_8/PR1_PRU0_PRU_R31_8/GPIO2_26) ; also on sheet 8
MMC1_CLK: C6.1 R32.2 ; also on sheet 6 8
MMC1_CMD: R33.2 ; also on sheet 6 8
MMC1_DAT0: R37.2 ; also on sheet 6 8
MMC1_DAT1: R38.2 ; also on sheet 6 8
MMC1_DAT2: R39.2 ; also on sheet 6 8
MMC1_DAT3: R40.2 ; also on sheet 6 8
MMC1_DAT4: R41.2 ; also on sheet 6 8
MMC1_DAT5: R42.2 ; also on sheet 6 8
MMC1_DAT6: R43.2 ; also on sheet 6 8
MMC1_DAT7: R44.2 ; also on sheet 6 8
OSC0_IN: C25.1 R17.1 U5.V10(OSC0_IN) Y2.1
OSC0_OUT: R17.2 R179.2 U5.U11(OSC0_OUT)
OSC0_OUT1: C26.1 R179.1 Y2.3
OSC1_IN: C21.2 R134.2 U5.A6(OSC1_IN) Y1.2
OSC1_OUT: R30.2 R134.1 U5.A4(OSC1_OUT)
OSC1_OUT1: C22.2 R30.1 Y1.1
PMIC_INT: U5.B18(NNMI) ; also on sheet 3
PMIC_POWR_EN: U5.C6(PMIC_POWER_EN) ; also on sheet 3
PMIC_RSTOUTn: R191.1 U5.B15(PORZn) U16.2(A) ; also on sheet 3
PROC_A15: R18.1 U5.A15(EVENT_INTR0/TIMER4/CLKOUT1/SPI1_CS1/PR1PRU1R31_16/EMU2/GPIO0_19)
PWR_BUT: R211.1 ; also on sheet 8
PWR_ST/GPIO1_9: U5.E17(UART0_RTSN/UART4_TXD/DCAN1_RX/I2C1_SCL/SPI1_D1/SPI1_CS0/PR1_EDC_SYNC1_OUT/GPIO1_9) ; also on sheet 8
RGMII1_RCLK: U5.L18(GMII1_RXCLK/UART2_TXD/RGMII1_RCLK/MMC0_DAT6/MMC1_DAT1/UART1_DSRN/MCASP0_FSX/GPIO3_10) ; also on sheet 7
RGMII1_RCTL: U5.J17(GMII1_RXDV/LCD_MEMORY_CLK/RGMII1_RCTL/UART5_TXD/MCASP1_ACLKX/MMC2_DAT0/MCASP0_ACLKR/GPIO3_4) ; also on sheet 7
RGMII1_RD0: U5.M16(GMII1_RXD0/RMII1_RXD0/RGMII1_RD0/MCASP1_AHCLKX/MCASP1_AHCLKR/MCASP1_ACLKR/MCASP0_AXR3/GPIO2_21) ; also on sheet 7
RGMII1_RD1: U5.L15(GMII1_RXD1/RMII1_RXD1/RGMII1_RD1/MCASP1_AXR3/MCASP1_FSR/EQEP0_STROBE/MMC2_CLK/GPIO2_20) ; also on sheet 7
RGMII1_RD2: U5.L16(GMII1_RXD2/UART3_TXD/RGMII1_RD2/MMC0_DAT4/MMC1_DAT3/UART1_RIN/MCASP0_AXR1/GPIO2_19) ; also on sheet 7
RGMII1_RD3: U5.L17(GMII1_RXD3/UART3_RXD/RGMII1_RD3/MMC0_DAT5/MMC1_DAT2/UART1_DTRN/MCASP0_AXR0/GPIO2_18) ; also on sheet 7
RGMII1_TCTL: U5.J16(GMII1_TXEN/RMII1_TXEN/RGMII1_TCTL/TIMER4/MCASP1_AXR0/EQEP0_INDEX/MMC2_CMD/GPIO3_3) ; also on sheet 7
RGMII1_TD0: U5.K17(GMII1_TXD0/RMII1_TXD0/RGMII1_TD0/MCASP1_AXR2/MCASP1_ACLKR/EQEP0B_IN/MMC1_CLK/GPIO0_28) ; also on sheet 7
RGMII1_TD1: U5.K16(GMII1_TXD1/RMII1_TXD1/RGMII1_TD1/MCASP1_FSR/MCASP1_AXR1/EQEP0A_IN/MMC1_CMD/GPIO0_21) ; also on sheet 7
RGMII1_TD2: U5.K15(GMII1_TXD2/DCAN0_RX/RGMII1_TD2/UART4_TXD/MCASP1_AXR0/MMC2_DAT2/MCASP0_AHCLKX/GPIO0_17) ; also on sheet 7
RGMII1_TD3: U5.J18(GMII1_TXD3/DCAN0_TX/RGMII1_TD3/UART4_RXD/MCASP1_FSX/MMC2_DAT1/MCASP0_FSR/GPIO0_16) ; also on sheet 7
RGMII1_TXCLK: U5.K18(GMII1_TXCLK/UART2_RXD/RGMII1_TCLK/MMC0_DAT7/MMC1_DAT0/UART1_DCDN/MCASP0_ACLKX/GPIO3_9) ; also on sheet 7
RMII1_REFCLK: U5.H18(RMII1_REFCLK/XDMA_EVENT_INTR2/SPI1_CS0/UART5_TXD/MCASP1_AXR3/MMC0_POW/MCASP1_AHCLKX/GPIO0_29) ; also on sheet 7
RTC_PORZn: R191.2 U5.B5(RTC_PORZn)
SPI1_CS0: U5.C12(MCASP0_AHCLKR/EHRPWM0_SYNCI_O/MCASP0_AXR2/SPI1_CS0/ECAP2_IN_PWM2_OUT/PR1_PRU0_PRU_R30_3/PR1_PRU0_PRU_R31_3/GPIO3_17) ; also on sheet 8
SPI1_D0: U5.B13(MCASP0_FSX/EHRPWM0B//SPI1_D0/MMC1_SDCD/PR1_PRU0_PRU_R30_1/PR1_PRU0_PRU_R31_1/GPIO3_15) ; also on sheet 8
SPI1_D1: U5.D12(MCASP0_AXR0/EHRPWM0_TRIPZONE_INPUT//SPI1_D1/MMC2_SDCD/PR1_PRU0_PRU_R30_2/PR1_PRU0_PRU_R31_2/GPIO3_16) ; also on sheet 8
SPI1_SCLK: U5.A13(MCASP0_ACLKX/EHRPWM0A//SPI1_SCLK/MMC0_SDCD/PR1_PRU0_PRU_R30_0/PR1_PRU0_PRU_R31_0/GPIO3_14) ; also on sheet 8
SYS_5V: C34.1 U8.2(IN1) U8.3(IN2) ; also on sheet 3 4 8
SYS_RESETn: C24.1 C30.1 D6.2 P2.15(SRST) R14.2 S1.2(B1) S1.4(B2) U5.A10(NRESET_INOUT) U16.4(Y) ; also on sheet 7 8
TESTOUT: TP3.1(TP) U5.A3(TESTOUT)
TIMER4: U5.R7(GPMC_ADVN_ALE/TIMER4/GPIO2_2) ; also on sheet 8
TIMER5: U5.T6(GPMC_BE0N_CLE/TIMER5/GPIO2_5) ; also on sheet 8
TIMER6: U5.U6(GPMC_WEN/TIMER6/GPIO2_4) ; also on sheet 8
TIMER7: U5.T7(GPMC_OEN_REN/TIMER7/EMU4/GPIO2_3) ; also on sheet 8
U5_R13: R160.1 U5.R13(GPMC_A0/GMII2_TXEN/RGMII2_TCTL/RMII2_TXEN/GPMC_A16/PR1_MII_MT1_CLK/EHRPWM1_TRIPZONE_INPUT/GPIO1_16)
U5_T13: R161.1 U5.T13(GPMC_CSN3/MMC2_CMD/PR1_MDIO_DATA/GPIO2_0)
UART0_RX: U5.E15(UART0_RXD/SPI1_CS0/DCAN0_TX/I2C2_SDA/ECAP2_IN_PWM2_OUT/PR1_PRU1_PRU_R30_14/PR1_PRU1_PRU_R31_14/GPIO1_10) U15.6(1Y)
UART0_TX: U5.E16(UART0_TXD/SPI1_CS1/DCAN0_RX/I2C2_SCL/ECAP1_IN_PWM1_OUT/PR1_PRU1_PRU_R30_15/PR1_PRU1_PRU_R31_15/GPIO1_11) U15.5(2A)
UART1_RXD: U5.D16(UART1_RXD/MMC1_SDWP/DCAN1_TX/I2C1_SDA//PR1_UART0_RXD/PR1_PRU1_PRU_R31_16/GPIO0_14) ; also on sheet 8
UART1_TXD: U5.D15(UART1_TXD/MMC2_SDWP/DCAN1_RX/I2C1_SCL//PR1_UART0_TXD/PR1_PRU0_PRU_R31_16/GPIO0_15) ; also on sheet 8
UART2_RXD: U5.A17(SPI0_SCLK/UART2_RXD/I2C2_SDA/EHRPWM0A/PR1_UART0_CTS_N/PR1_EDIO_SOF/EMU2/GPIO0_2) ; also on sheet 8
UART2_TXD: U5.B17(SPI0_D0/UART2_TXD/I2C2_SCL/EHRPWM0B/PR1_UART0_RTS_N/PR1_EDIO_LATCH_IN/EMU3/GPIO0_3) ; also on sheet 8
UART4_RXD: U5.T17(GPMC_WAIT0/GM112_CRS/GPMC_CSN4/RMII2_CRS_DV/MMC1_SDCD/PR1_MII1_RXDV/UART4_RXD/GPIO0_30) ; also on sheet 8
UART4_TXD: U5.U17(GPMC_WPN/GMII2_RXERR/GPMC_CSN5/RMII2_RXERR/MMC2_SDCD/PR1_MDIO_MDCLK/UART4_TXD/GPIO0_31) ; also on sheet 8
USB0_DM: L5.1 R204.1 U5.N18(USB0_DM)
USB0_DP: L5.4 R205.1 U5.N17(USB0_DP)
USB0_ID: TP6.1(TP) U5.P16(USB0_ID)
USB0_VBUS: D19.2(C) R159.2 U5.P15(USB0_VBUS)
USB1_DM: L4.1 R202.1 U5.R18(USB1_DM)
USB1_DP: L4.4 R203.1 U5.R17(USB1_DP)
USB1_DRVVBUS: R53.1 U5.F15(USB1_DRVVBUS/GPIO3_13) U8.4(EN)
USB1_ID: R49.2 U5.P17(USB1_ID)
USB1_OCn: R52.2 U5.T16(GPMC_A10/GMII2_RXD1/RGMII2_RD1/RMII2_RXD1/GPMC_A26/PR1_MII1_CRS/MCASP0_AXR0/GPIO1_26) U8.5(~{OC})
USB1_PWR: FB7.1 R36.2 U8.6(OUT3) U8.7(OUT2) U8.8(OUT1)
USB1_VBUS: D20.2(C) R36.1 U5.T18(USB1_VBUS)
USB_DC: P4.B4(A9/B4/VBUS) P4.B9(A4/B9/VBUS) R159.1 U11.4(IN) U11.5(IN1) U11.6(IN2) ; also on sheet 8
USR0: U5.V15(GPMC_A5/GMII2_TXD0/RGMII2_TD0/RMII2_TXD0/GPMC_A21/PR1_MII1_RXD3/EQEP1B_IN/GPIO1_21) ; also on sheet 4
USR1: U5.U15(GPMC_A6/GMII2_TXCLK/RGMII2_TCLK/MMC2_DAT4/GPMC_A22/PR1_MII1_RXD2/EQEP1_INDEX/GPIO1_22) ; also on sheet 4
USR2: U5.T15(GPMC_A7/GMII2_RXCLK/RGMII2_RCLK/MMC2_DAT5/GPMC_A23/PR1_MII1_RXD1/EQEP1_STROBE/GPIO1_23) ; also on sheet 4
USR3: U5.V16(GPMC_A8/GMII2_RXD3/RGMII2_RD3/MMC2_DAT6/GPMC_A24/PR1_MII1_RXD0/MCASP0_ACLKX/GPIO1_24) ; also on sheet 4
VREFP_ADC: C31.1 C32.1 C33.1 R27.2 U5.B9(VREFP)
WAKEUP: D13.2 R26.2 R211.2 S3.2(B1) S3.4(B2) U5.C5(EXT_WAKEUP)
XDMA_EVENT_INTR0: P2.17(EMU2) R18.2
N21688701: R169.1 R170.1 U5.U16(GPMC_A9/GMII2_RXD2/RGMII2_RD2/MMC2_DAT7/GPMC_A25/PR1_MII_MR1_CLK/MCASP0_FSX/GPIO1_25)
N22248684: R167.1 Y4.3(CLK)
N22287501: R162.1 U3.4(Y)
N22287555: U3.2(A) U5.R14(GPMC_A4/GMII2_TXD1/RGMII2_TD1/RMII2_TXD1/GPMC_A20/PR1_MII1_TXD0/EQEP1A_IN/GPIO1_20)
N23148935: D10.2(C) R182.1

Not connected (* = marked no-connect by the designer): J1 2* 3* 6*; P2 6(NC)*; P4 A8(SBU1)* B8(SBU2)*; U3 1(NC)*; U5 F16(USB0_DRVVBUS/GPIO0_18)* H16(GMII1_COL/RMII2_REFCLK/SPI1_SCLK/UART5_RXD/MCASP1_AXR2/MMC2_DAT3/MCASP0_AXR2/GPIO3_0)* J15(GMII1_RXERR/RMII1_RXERR/SPI1_D1/I2C1_SCL/MCASP1_FSX/UART5_RTSN/UART2_TXD/GPIO3_2)* M5(VPP)* M15(USB0_CE)* P18(USB1_CE)*; U16 1(NC)*

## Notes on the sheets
sheet 9
- Reset Button
- 1.8V
- VDDSHV6 = 3.3V
- VDDSHV6 = 3.3V, VIH = 1.35V
- VDDS_RTC = 1.8V
- VDDSHV6 = 3.3V
- Layout Note:
- Place R32,R33,C6 Close To MPU.
- H
- External clock to
  the McASP0
  interface.
- Oscillator can be disabled via
  SW for power down modes or if
  GPIO3_21 needs to be used.
- JTAG Connector
sheet 10
- Wake-Up Button
- USB Device & Power In
- Type A Connector
- USB Host
- Type C Connector
- Debug UART
- Layout Note:
- Add Silkscreen:
- J1: Debug
- Pin1: GND
- Pin2: NC
- Pin3: NC
- Pin4: RX
- Pin5: TX
- Pin6: NC
- Layout Note:
- Place TVS close to Connector.
- Plated Hole
sheet 11
- 0.912V to 1.144V
- Type: 1.1V
- Max: 400mA
- Power
- Max: 50mA
- Max: 50mA
- Max: 50mA
- 0.912V to 1.378V
- Type: 1.1V
- Max: 1A
- Max: 50mA
- Max: 50mA
- Max: 100mA
- Max: 10mA
- Max: 10mA
- Max: 50mA
- Max: 10mA
- Max: 25mA
- Max: 10mA
- Max: 25mA
- Max: 10mA
- Max: 20mA
- Max: 5mA
- Max: 5mA
- Max: 250mA
